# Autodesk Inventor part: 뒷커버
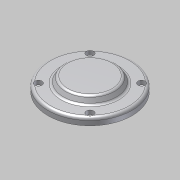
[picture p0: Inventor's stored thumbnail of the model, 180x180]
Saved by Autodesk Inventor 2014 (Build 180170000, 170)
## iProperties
Created: 2013-02
Part Number: 뒷커버
Document SubType Name: Modeling
Designer: 한국산업디자인학원[gmhk.co.kr]
Density: 1 g/cm^3
Material: 일반
Appearance: 기본값
Author: 한국산업디자인학원[gmhk.co.kr]
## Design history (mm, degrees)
sketch "스케치1"
  geometry: C1 r 30 at (0, 0) reference; C2 r 46 at (0, 0); A1 r 91.05 centre (0, -48.55) between (34.185, 35.839) and (-34.185, 35.839) reference; A2 r 91.05 centre (48.55, 0) between (-35.839, 34.185) and (-35.839, -34.185) reference; A3 r 3 centre (-33.058, 33.058) between (-34.185, 35.839) and (-35.839, 34.185) reference; A4 r 3 centre (33.058, 33.058) between (35.839, 34.185) and (34.185, 35.839) reference; A5 r 91.05 centre (-48.55, 0) between (35.839, -34.185) and (35.839, 34.185) reference; A6 r 3 centre (33.058, -33.058) between (34.185, -35.839) and (35.839, -34.185) reference; A7 r 91.05 centre (0, 48.55) between (-34.185, -35.839) and (34.185, -35.839) reference; A8 r 3 centre (-33.058, -33.058) between (-35.839, -34.185) and (-34.185, -35.839) reference; 1 further point
  constraints: 1 centre point, 1 coincident
  dimensions: "d37" = 92 diameter of C2
  node "참조1"
  node "참조2"
  node "참조3"
  node "참조4"
  node "참조5"
  node "참조6"
  node "참조7"
  node "참조8"
  node "참조9"
extrude "돌출1" new body sketch "스케치1" distance "d0" = 8; taper "d1" = 0 deg
sketch "스케치2"
  geometry: C1 r 30 at (0, 0); 1 further point
  constraints: 1 centre point, 1 coincident
  dimensions: "d2" = 60 diameter of C1
extrude "돌출2" join sketch "스케치2" distance "d3" = 7; taper "d4" = -30 deg
sketch "스케치3"
  geometry: C1 r 1.621 at (28.284, 28.284) reference; C2 r 1.621 at (-28.284, 28.284) reference; C3 r 1.621 at (-28.284, -28.284) reference; C4 r 1.621 at (28.284, -28.284) reference; 1 further point
hole "구멍2" sketch "스케치3" at (28.284, 28.284), (28.284, -28.284), (-28.284, -28.284), (-28.284, 28.284) diameter "d14" = 4.5; stored, may be unused: countersink angle "d18" = 90 deg, drill point angle "d20" = 118 deg; dims "d15" = 6, "d16" = 8, "d17" = 4.4, "d19" = 20
extrude "돌출3" join sketch "스케치1" distance "d21" = 12; taper "d22" = 0 deg
hole "구멍3" diameter "d25" = 30; stored, may be unused: countersink angle "d29" = 90 deg, drill point angle "d31" = 0 deg; dims "d23" = 10, "d24" = 10, "d26" = 6, "d27" = 40, "d28" = 12, "d30" = 15
fillet "모깎기1" dims "d32" = 3, "d33" = 0.3
chamfer "모따기1" distance "d34" = 1; stored, may be unused: second distance "d35" = 2, angle "d36" = 45 deg
fillet "모깎기2" dims "d38" = 3
node "솔리드1"
node "참조10"
node "참조11"
node "참조12"
node "참조13"
